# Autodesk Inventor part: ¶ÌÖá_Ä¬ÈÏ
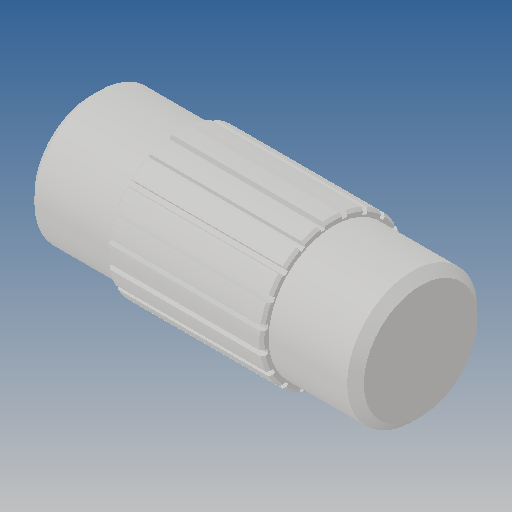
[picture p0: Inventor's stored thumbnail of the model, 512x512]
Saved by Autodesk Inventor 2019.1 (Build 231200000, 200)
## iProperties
Created: 2012-10
Part Number: ¶ÌÖá_Ä¬ÈÏ
Material: Ogólny
Document SubType Name: Modeling
Designer: CADENGINEERING4
Density: 1 g/cm^3
Appearance: Domyślna
Author: CADENGINEERING4
Revision Number: ÈÎºÎ
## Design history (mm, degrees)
feature "NONE"
node "Bryła1"
